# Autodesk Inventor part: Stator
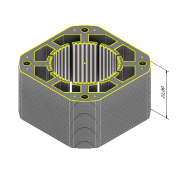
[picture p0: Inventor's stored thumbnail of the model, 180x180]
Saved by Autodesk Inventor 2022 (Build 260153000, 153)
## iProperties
Created: 2020-10
Part Number: Stator
Material: Generico
Document SubType Name: Modeling
Designer: admin
Density: 1 g/cm^3
Appearance: Default
Sending System: SolidWorks 2020
Last Author: Simon
Last Saved: 2020-10-31
Author: admin
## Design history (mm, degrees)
node "Annotazioni"
  node "Quota lineare 1" dims "d2" = 22 (derived)
fillet "LPattern3"
fillet "Fillet9"
fillet "Fillet18"
fillet "Fillet20"
fillet "Fillet22"
node "Fillet23"
fillet "Fillet29"
sketch "Schizzo1"
  geometry: L1 (-8.246, 8.246)-(-8.246, 33.544) reference; L2 (25.298, 0)-(0, 0) reference; L3 (33.544, 33.544)-(33.544, 8.246) reference; L4 (0, 41.79)-(25.298, 41.79) reference; L5 (1.454, 11.68)-(-1.776, 8.45) reference; L6 (-6.351, 13.025)-(-1.776, 8.45) reference; L7 (-6.351, 19.495)-(-6.351, 13.025) reference; L8 (-6.351, 19.495)-(-1.783, 19.495) reference; L9 (0.387, 16.578)-(-1.028, 16.08) reference; L10 (-1.028, 25.71)-(0.387, 25.212) reference; L11 (-1.783, 22.295)-(-6.351, 22.295) reference; L12 (-6.351, 28.765)-(-6.351, 22.295) reference; L13 (-1.776, 33.34)-(-6.351, 28.765) reference; L14 (-1.776, 33.34)-(1.454, 30.11) reference; L15 (0.926, 26.513)-(-0.427, 27.161) reference; L16 (6.383, 33.971)-(7.031, 32.618) reference; L17 (3.434, 32.09)-(0.204, 35.32) reference; L18 (4.779, 39.895)-(0.204, 35.32) reference; L19 (11.249, 39.895)-(4.779, 39.895) reference; L20 (11.249, 39.895)-(11.249, 35.327) reference; L21 (8.332, 33.157)-(7.834, 34.572) reference; L22 (17.465, 34.572)-(16.966, 33.157) reference; L23 (14.049, 35.327)-(14.049, 39.895) reference; L24 (20.519, 39.895)-(14.049, 39.895) reference; L25 (25.094, 35.32)-(20.519, 39.895) reference; L26 (25.094, 35.32)-(21.864, 32.09) reference; L27 (18.267, 32.618)-(18.915, 33.971) reference; L28 (25.725, 27.161)-(24.373, 26.513) reference; L29 (23.844, 30.11)-(27.074, 33.34) reference; L30 (31.649, 28.765)-(27.074, 33.34) reference; L31 (31.649, 22.295)-(31.649, 28.765) reference; L32 (31.649, 22.295)-(27.081, 22.295) reference; L33 (24.911, 25.212)-(26.326, 25.71) reference; L34 (26.326, 16.08)-(24.911, 16.578) reference; L35 (27.081, 19.495)-(31.649, 19.495) reference; L36 (31.649, 13.025)-(31.649, 19.495) reference; L37 (27.074, 8.45)-(31.649, 13.025) reference; L38 (27.074, 8.45)-(23.844, 11.68) reference; L39 (24.373, 15.277)-(25.725, 14.629) reference; L40 (18.915, 7.819)-(18.267, 9.172) reference; L41 (21.864, 9.7)-(25.094, 6.47) reference; L42 (20.519, 1.895)-(25.094, 6.47) reference; L43 (14.049, 1.895)-(20.519, 1.895) reference; L44 (14.049, 1.895)-(14.049, 6.463) reference; L45 (16.966, 8.633)-(17.465, 7.218) reference; L46 (7.834, 7.218)-(8.332, 8.633) reference; L47 (11.249, 6.463)-(11.249, 1.895) reference; L48 (4.779, 1.895)-(11.249, 1.895) reference; L49 (0.204, 6.47)-(4.779, 1.895) reference; L50 (0.204, 6.47)-(3.434, 9.7) reference; L51 (7.031, 9.172)-(6.383, 7.819) reference; L52 (-0.427, 14.629)-(0.926, 15.277) reference; C1 r 1.5 at (28.149, 5.395) reference; C2 r 1.5 at (-2.851, 5.395) reference; C3 r 1.5 at (-2.851, 36.395) reference; C4 r 1.5 at (28.149, 36.395) reference; A1 r 2.895 centre (-5.351, 8.246) between (-8.246, 8.246) and (-7.719, 6.581) reference; A2 r 24.895 centre (12.649, 20.895) between (-7.719, 6.581) and (-1.664, 0.526) reference; A3 r 2.895 centre (0, 2.895) between (-1.664, 0.526) and (0, 0) reference; A4 r 2.895 centre (25.298, 2.895) between (25.298, 0) and (26.963, 0.526) reference; A5 r 24.895 centre (12.649, 20.895) between (26.963, 0.526) and (33.018, 6.581) reference; A6 r 2.895 centre (30.649, 8.246) between (33.018, 6.581) and (33.544, 8.246) reference; A7 r 2.895 centre (30.649, 33.544) between (33.544, 33.544) and (33.018, 35.209) reference; A8 r 24.895 centre (12.649, 20.895) between (33.018, 35.209) and (26.963, 41.264) reference; A9 r 2.895 centre (25.298, 38.895) between (26.963, 41.264) and (25.298, 41.79) reference; A10 r 2.895 centre (0, 38.895) between (0, 41.79) and (-1.664, 41.264) reference; A11 r 24.895 centre (12.649, 20.895) between (-1.664, 41.264) and (-7.719, 35.209) reference; A12 r 2.895 centre (-5.351, 33.544) between (-7.719, 35.209) and (-8.246, 33.544) reference; A13 r 14.5 centre (12.649, 20.895) between (-1.783, 19.495) and (-1.028, 16.08) reference; A14 r 13 centre (12.649, 20.895) between (0.191, 17.18) and (0.387, 16.578) reference; A15 r 0.5 centre (0.058, 17.662) between (-0.057, 18.149) and (0.191, 17.18) reference; A16 r 13 centre (12.649, 20.895) between (-0.176, 18.771) and (-0.057, 18.149) reference; A17 r 0.5 centre (-0.248, 19.266) between (-0.301, 19.763) and (-0.176, 18.771) reference; A18 r 13 centre (12.649, 20.895) between (-0.341, 20.395) and (-0.301, 19.763) reference; A19 r 0.5 centre (-0.351, 20.895) between (-0.341, 21.395) and (-0.341, 20.395) reference; A20 r 13 centre (12.649, 20.895) between (-0.301, 22.027) and (-0.341, 21.395) reference; A21 r 0.5 centre (-0.248, 22.524) between (-0.176, 23.019) and (-0.301, 22.027) reference; A22 r 13 centre (12.649, 20.895) between (-0.057, 23.641) and (-0.176, 23.019) reference; A23 r 0.5 centre (0.058, 24.128) between (0.191, 24.61) and (-0.057, 23.641) reference; A24 r 13 centre (12.649, 20.895) between (0.387, 25.212) and (0.191, 24.61) reference; A25 r 14.5 centre (12.649, 20.895) between (-1.028, 25.71) and (-1.783, 22.295) reference; A26 r 14.5 centre (12.649, 20.895) between (1.454, 30.11) and (-0.427, 27.161) reference; A27 r 13 centre (12.649, 20.895) between (1.213, 27.077) and (0.926, 26.513) reference; A28 r 0.5 centre (1.459, 27.512) between (1.722, 27.938) and (1.213, 27.077) reference; A29 r 13 centre (12.649, 20.895) between (2.078, 28.462) and (1.722, 27.938) reference; A30 r 0.5 centre (2.377, 28.863) between (2.691, 29.252) and (2.078, 28.462) reference; A31 r 13 centre (12.649, 20.895) between (3.11, 29.727) and (2.691, 29.252) reference; A32 r 0.5 centre (3.457, 30.087) between (3.817, 30.434) and (3.11, 29.727) reference; A33 r 13 centre (12.649, 20.895) between (4.292, 30.853) and (3.817, 30.434) reference; A34 r 0.5 centre (4.681, 31.167) between (5.082, 31.466) and (4.292, 30.853) reference; A35 r 13 centre (12.649, 20.895) between (5.606, 31.822) and (5.082, 31.466) reference; A36 r 0.5 centre (6.032, 32.085) between (6.467, 32.331) and (5.606, 31.822) reference; A37 r 13 centre (12.649, 20.895) between (7.031, 32.618) and (6.467, 32.331) reference; A38 r 14.5 centre (12.649, 20.895) between (6.383, 33.971) and (3.434, 32.09) reference; A39 r 14.5 centre (12.649, 20.895) between (11.249, 35.327) and (7.834, 34.572) reference; A40 r 13 centre (12.649, 20.895) between (8.934, 33.353) and (8.332, 33.157) reference; A41 r 0.5 centre (9.416, 33.487) between (9.903, 33.602) and (8.934, 33.353) reference; A42 r 13 centre (12.649, 20.895) between (10.525, 33.72) and (9.903, 33.602) reference; A43 r 0.5 centre (11.02, 33.792) between (11.517, 33.846) and (10.525, 33.72) reference; A44 r 13 centre (12.649, 20.895) between (12.149, 33.885) and (11.517, 33.846) reference; A45 r 0.5 centre (12.649, 33.895) between (13.149, 33.885) and (12.149, 33.885) reference; A46 r 13 centre (12.649, 20.895) between (13.781, 33.846) and (13.149, 33.885) reference; A47 r 0.5 centre (14.278, 33.792) between (14.773, 33.72) and (13.781, 33.846) reference; A48 r 13 centre (12.649, 20.895) between (15.395, 33.602) and (14.773, 33.72) reference; A49 r 0.5 centre (15.882, 33.487) between (16.364, 33.353) and (15.395, 33.602) reference; A50 r 13 centre (12.649, 20.895) between (16.966, 33.157) and (16.364, 33.353) reference; A51 r 14.5 centre (12.649, 20.895) between (17.465, 34.572) and (14.049, 35.327) reference; A52 r 14.5 centre (12.649, 20.895) between (21.864, 32.09) and (18.915, 33.971) reference; A53 r 13 centre (12.649, 20.895) between (18.831, 32.331) and (18.267, 32.618) reference; A54 r 0.5 centre (19.267, 32.085) between (19.692, 31.822) and (18.831, 32.331) reference; A55 r 13 centre (12.649, 20.895) between (20.216, 31.466) and (19.692, 31.822) reference; A56 r 0.5 centre (20.617, 31.167) between (21.006, 30.853) and (20.216, 31.466) reference; A57 r 13 centre (12.649, 20.895) between (21.481, 30.434) and (21.006, 30.853) reference; A58 r 0.5 centre (21.841, 30.087) between (22.188, 29.727) and (21.481, 30.434) reference; A59 r 13 centre (12.649, 20.895) between (22.607, 29.252) and (22.188, 29.727) reference; A60 r 0.5 centre (22.921, 28.863) between (23.22, 28.462) and (22.607, 29.252) reference; A61 r 13 centre (12.649, 20.895) between (23.576, 27.938) and (23.22, 28.462) reference; A62 r 0.5 centre (23.839, 27.512) between (24.085, 27.077) and (23.576, 27.938) reference; A63 r 13 centre (12.649, 20.895) between (24.373, 26.513) and (24.085, 27.077) reference; A64 r 14.5 centre (12.649, 20.895) between (25.725, 27.161) and (23.844, 30.11) reference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; 1 further point
  node "Linea chiusa proiettata1"
node "Solido1"
node "Solido2"
node "Solido3"
node "Solido4"
node "Solido5"
node "Solido6"
node "Solido7"
other parameters: "d0" = 0.57771 (derived), "d1" = 8.44325 (derived)
